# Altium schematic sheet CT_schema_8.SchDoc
size 287 x 160 mm
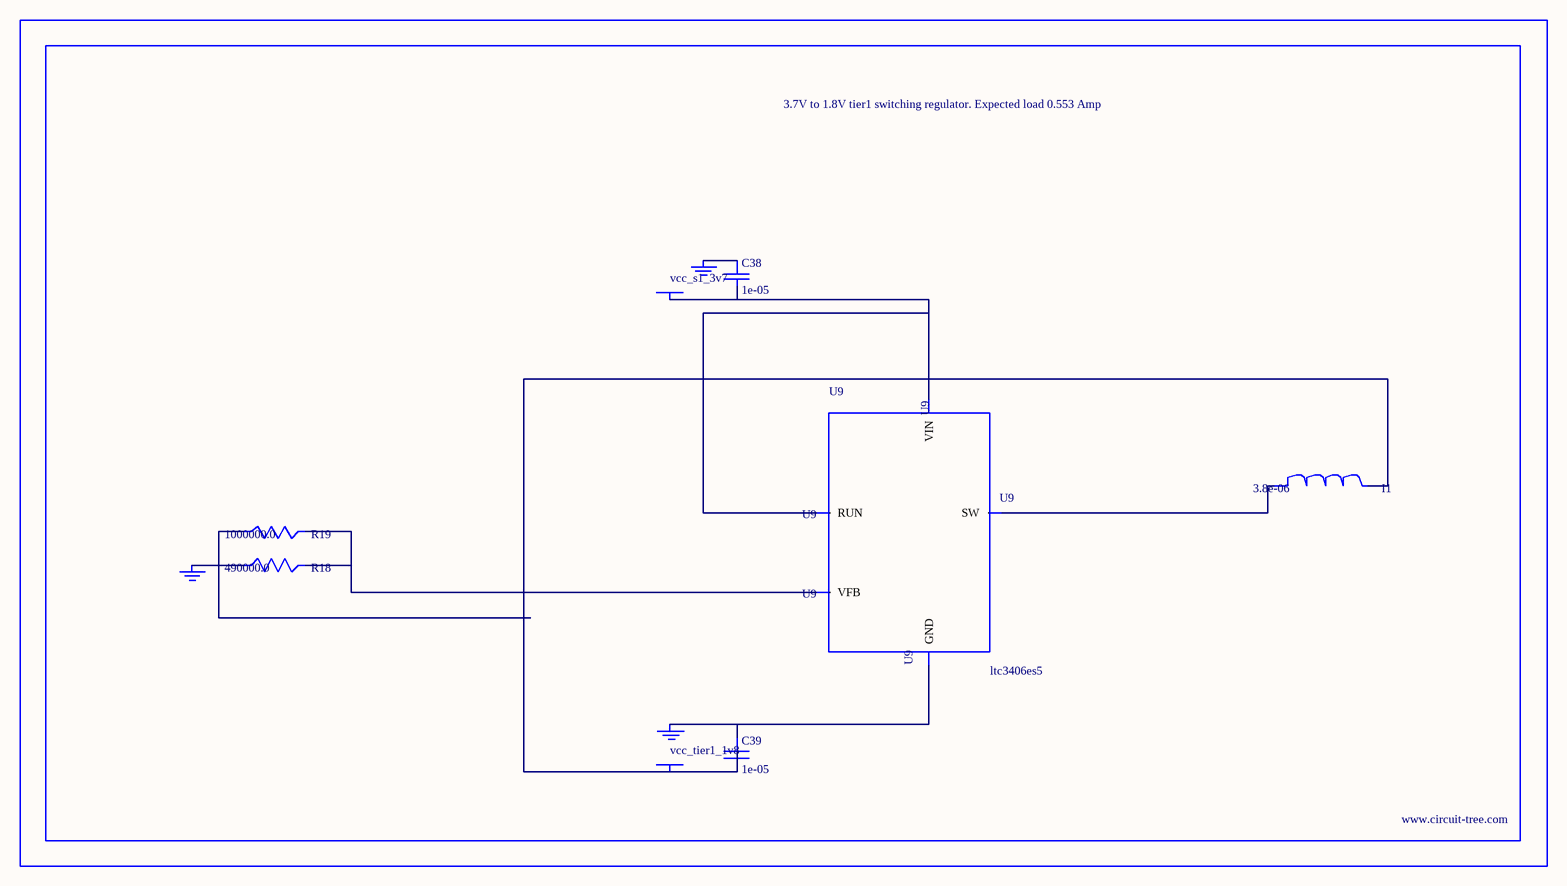
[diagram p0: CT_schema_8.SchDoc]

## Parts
BORDER7  (no value)
C38  1e-05  [C0805]
C39  1e-05  [C0805]
GND_INSTANCE_7_0  (no value)
GND_INSTANCE_7_1  (no value)
GND_INSTANCE_7_2  (no value)
I1  3.8e-06  [DR1040]
POWER_INSTANCE_7_0  vcc_tier1_1v8
POWER_INSTANCE_7_1  vcc_s1_3v7
R18  490000.0  [R0603]
R19  1000000.0  [R0603]
U9  ltc3406es5  [TSOT-23-5]

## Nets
NetC38_1: C38.1 GND_INSTANCE_7_1.0(GND)
NetC38_2: C38.2 POWER_INSTANCE_7_1.0(PWR) U9.1(RUN) U9.4(VIN)
NetC39_1: C39.1 GND_INSTANCE_7_0.0(GND) U9.2(GND)
NetC39_2: C39.2 I1.2 POWER_INSTANCE_7_0.0(PWR) R19.1
NetGND_INSTANCE_7_2_0: GND_INSTANCE_7_2.0(GND) R18.1
NetI1_1: I1.1 U9.3(SW)
NetR18_2: R18.2 R19.2 U9.5(VFB)

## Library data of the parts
BORDER7 = BORDER_PAGE7
C38 C39 = C0805C106K8RACTU
GND_INSTANCE_7_0-GND_INSTANCE_7_2 = GND
I1 = DR1040-3R8-R
POWER_INSTANCE_7_0 POWER_INSTANCE_7_1 = PWR
R18 = R18
R19 = RC0603JR-071ML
